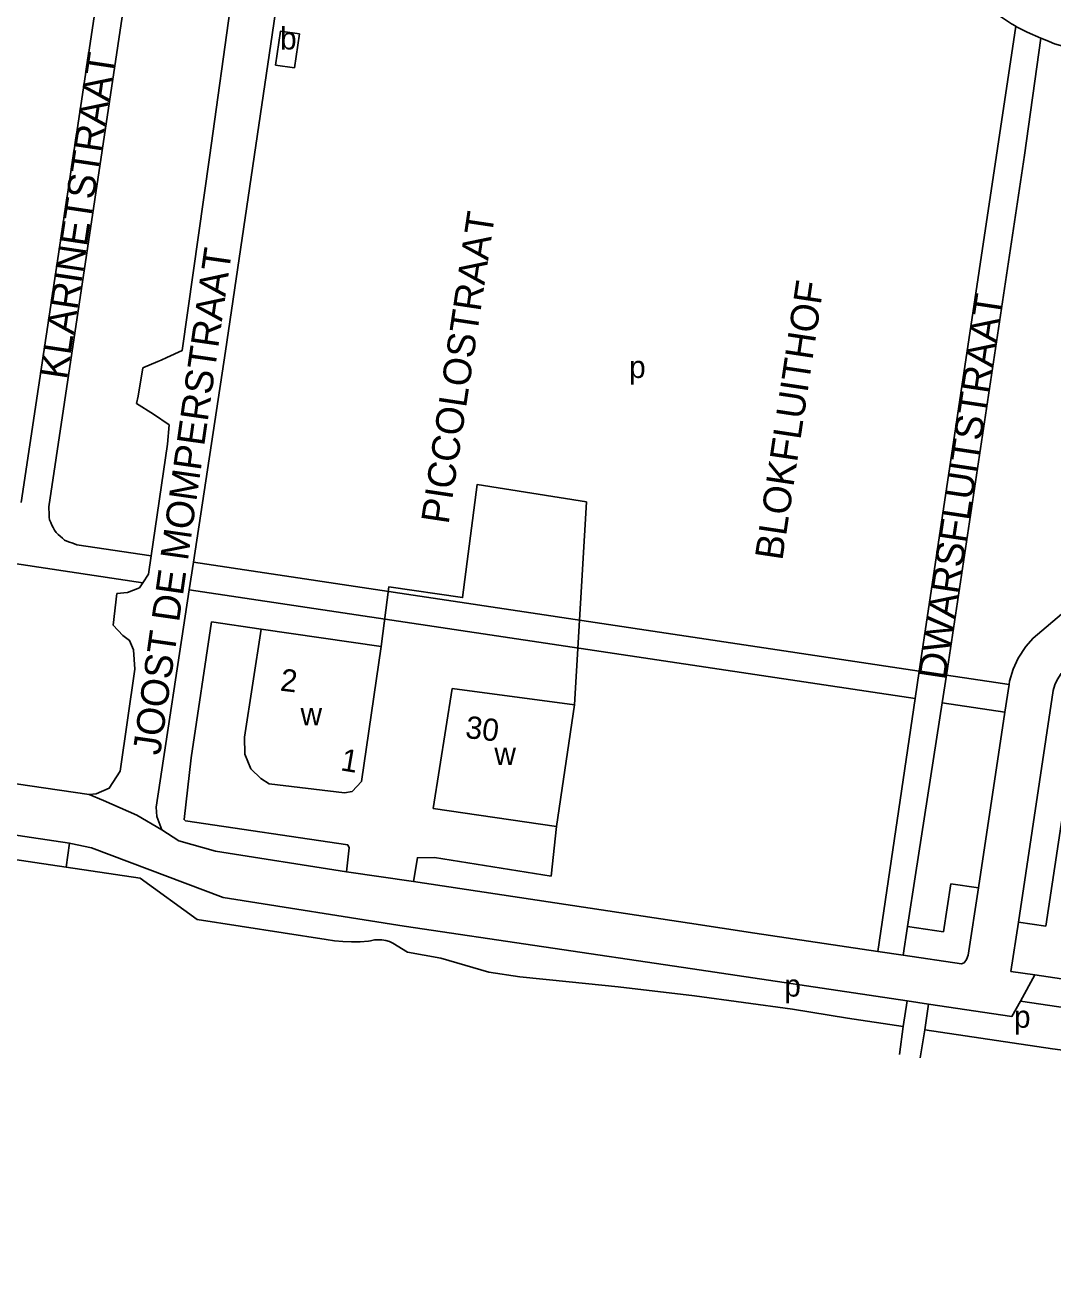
# Model space of a CAD drawing. Extents: x 163012 to 165277, y 382513 to 383987.
# Drawn here: x 164465.3 to 164649.9, y 382601.5 to 382827.9 of the extents above; entities that cross this region are included whole.
import ezdxf

# ---------------------------------------------------------------- set-up
doc = ezdxf.new("R2010")
doc.units = 0
for name, color, linetype in [('BLT_Basislijn', 7, 'Continuous'), ('BLT_Bebouwing', 7, 'Continuous'), ('BLT_Centroide', 7, 'Continuous'), ('BLT_Huisnummer', 7, 'Continuous'), ('BLT_Huisnummer_reeks', 7, 'Continuous'), ('BLT_Plantopo', 7, 'Continuous'), ('BLT_Straatnaam', 7, 'Continuous'), ('BLT_Vlakafsluiter', 7, 'Continuous')]:
    doc.layers.add(name, color=color, linetype=linetype)

msp = doc.modelspace()

# ---------------------------------------------------------------- linework, layer by layer
at = {"layer": 'BLT_Basislijn'}
for p, q in [((164498.41, 382804.11), (164503.27, 382838.72)), ((164644.88, 382804.57), (164647.78, 382825.58)), ((164486.49, 382766.37), (164485.6, 382761.24)), ((164486.49, 382766.37), (164489.17, 382767.47)), ((164485.35, 382759.94), (164485.6, 382761.24)), ((164485.35, 382759.94), (164488.37, 382758.01)), ((164481.81, 382725.81), (164481.16, 382720.15)), ((164481.81, 382725.81), (164483.72, 382726.02)), ((164481.16, 382720.15), (164482.88, 382718.29)), ((164507.71, 382719.39), (164529.29, 382716.27)), ((164542.06, 382708.77), (164538.65, 382687.21)), ((164542.06, 382708.77), (164563.99, 382705.82)), ((164563.99, 382705.82), (164560.8, 382683.95)), ((164538.65, 382687.21), (164560.8, 382683.95)), ((164472.71, 382676.64), (164418.34, 382684.73)), ((164560.8, 382683.95), (164559.83, 382675.03)), ((164472.71, 382676.64), (164473.3, 382680.95)), ((164523.03, 382675.81), (164535.08, 382674.05)), ((164535.08, 382674.05), (164584.68, 382666.58)), ((164631.65, 382673.68), (164636.59, 382672.94)), ((164519.43, 382663.67), (164496.2, 382667.24)), ((164533.41, 382666.08), (164583.59, 382658.63)), ((164623.85, 382665.98), (164623.05, 382660.82)), ((164623.85, 382665.98), (164630.34, 382665.02)), ((164643.76, 382666.8), (164648.7, 382666.05)), ((164596.42, 382664.78), (164618.52, 382661.5)), ((164618.52, 382661.5), (164623.05, 382660.82)), ((164623.05, 382660.82), (164633.54, 382659.27)), ((164583.59, 382658.63), (164623.77, 382652.64)), ((164646.72, 382657.3), (164691.53, 382650.62)), ((164623.09, 382648.02), (164623.77, 382652.64)), ((164626.93, 382647.45), (164627.61, 382652.06)), ((164622.39, 382643.02), (164623.09, 382648.02)), ((164626.12, 382642.42), (164626.93, 382647.45))]:
    msp.add_line(p, q, dxfattribs=at)
for points in [[(164511.39, 382837.58), (164501.34, 382769.35), (164495.56, 382731.44)], [(164639.31, 382830.29), (164642.52, 382828.15), (164643.29, 382827.72)], [(164626.81, 382717.82), (164643.29, 382827.72)], [(164643.29, 382827.72), (164643.45, 382827.63), (164644.38, 382827.11), (164645.33, 382826.62), (164647.78, 382825.58)], [(164647.78, 382825.58), (164648.29, 382825.36), (164649.28, 382824.94), (164650.28, 382824.57), (164651.31, 382824.25), (164652.33, 382823.93), (164653.36, 382823.62), (164654.38, 382823.3), (164655.42, 382823.06), (164656.47, 382822.85), (164657.51, 382822.64), (164658.56, 382822.42), (164659.6, 382822.21)], [(164642.1, 382709.46), (164642.2, 382710.08), (164642.8, 382712.21), (164643.72, 382714.19), (164645.09, 382716.27), (164646.41, 382717.79), (164753.19, 382808.18)], [(164490.8, 382768.2), (164493.55, 382769.49), (164498.41, 382804.11)], [(164644.88, 382804.57), (164630.87, 382711.15)], [(164643.76, 382666.8), (164650.03, 382708.38), (164650.32, 382709.41), (164650.73, 382710.29), (164651.48, 382711.43), (164652.04, 382712.07), (164758.95, 382802.57), (164761.34, 382804.28), (164762.45, 382804.76), (164763.28, 382804.91), (164766.44, 382804.62), (164769.71, 382804.13)], [(164489.17, 382767.47), (164489.76, 382767.72), (164490.8, 382768.2)], [(164487.96, 382732.58), (164490.92, 382752.64), (164491.18, 382756.1), (164488.37, 382758.01)], [(164529.29, 382716.27), (164530.68, 382727.01), (164543.9, 382725.08), (164546.51, 382745.37), (164566.16, 382742.25), (164563.99, 382705.82)], [(164486.46, 382727.74), (164487.47, 382729.3), (164487.96, 382732.58)], [(164495.56, 382731.44), (164494.8, 382726.49)], [(164483.72, 382726.02), (164485.84, 382726.81), (164486.46, 382727.74)], [(164494.8, 382726.49), (164488.85, 382687.46), (164488.96, 382685.77), (164489.89, 382683.35)], [(164187.08, 382723.68), (164473.3, 382680.95)], [(164507.71, 382719.39), (164498.82, 382720.72), (164495.16, 382696.29), (164493.88, 382685.21), (164494.11, 382684.99), (164523.28, 382680.64), (164523.52, 382680.11), (164523.03, 382675.81)], [(164482.88, 382718.29), (164484.08, 382717.37), (164484.78, 382715.68), (164485.03, 382712.22), (164482.37, 382693.89), (164480.43, 382690.85), (164478.1, 382689.83), (164476.83, 382689.72)], [(164507.71, 382719.39), (164504.73, 382699.99), (164504.8, 382696.93), (164505.88, 382694.32), (164507.66, 382692.58), (164509.16, 382691.61), (164522.69, 382689.99), (164524.06, 382690.27), (164525.72, 382692.03), (164529.29, 382716.27)], [(164625.94, 382711.88), (164626.81, 382717.82)], [(164625.21, 382706.94), (164625.94, 382711.88)], [(164630.87, 382711.15), (164630.1, 382706.2)], [(164641.36, 382704.52), (164642.1, 382709.46)], [(164618.52, 382661.5), (164625.21, 382706.94)], [(164630.1, 382706.2), (164625.36, 382675.67)], [(164636.59, 382672.94), (164641.36, 382704.52)], [(164648.7, 382666.05), (164654.21, 382702.59)], [(164476.83, 382689.72), (164421.44, 382697.77), (164396.29, 382701.71)], [(164489.89, 382683.35), (164485.4, 382685.97), (164479.37, 382688.6), (164476.83, 382689.72)], [(164489.89, 382683.35), (164492.94, 382681.36), (164499.51, 382679.52), (164523.03, 382675.81)], [(164473.3, 382680.95), (164473.51, 382680.92), (164477.24, 382680.13), (164500.92, 382671.2)], [(164559.83, 382675.03), (164538.87, 382678.36), (164535.8, 382678.35), (164535.08, 382674.05)], [(164496.2, 382667.24), (164485.99, 382674.7), (164472.71, 382676.64)], [(164625.36, 382675.67), (164623.85, 382665.98)], [(164630.34, 382665.02), (164631.65, 382673.68)], [(164633.54, 382659.27), (164634.02, 382659.44), (164634.45, 382660.08), (164634.77, 382660.86), (164636.59, 382672.94)], [(164500.92, 382671.2), (164533.41, 382666.08)], [(164596.42, 382664.78), (164584.68, 382666.58)], [(164646.72, 382657.3), (164642.42, 382657.94), (164643.76, 382666.8)], [(164527.02, 382663.34), (164525.48, 382663.25), (164523.94, 382663.24), (164522.4, 382663.3), (164520.87, 382663.45), (164519.43, 382663.67)], [(164531.38, 382663.01), (164530.75, 382663.28), (164530.1, 382663.47), (164529.42, 382663.58), (164528.74, 382663.62), (164528.06, 382663.57), (164527.39, 382663.45), (164527.02, 382663.34)], [(164571.88, 382655.18), (164563.03, 382656.07), (164554.17, 382656.95), (164548.63, 382657.78), (164540, 382660.32), (164534.03, 382661.41), (164531.38, 382663.01)], [(164623.09, 382648.02), (164613.09, 382649.5), (164603.16, 382651.17), (164585.55, 382653.57), (164571.88, 382655.18)], [(164623.77, 382652.64), (164627.61, 382652.06)], [(164627.61, 382652.06), (164642.6, 382649.83), (164644.12, 382652.59)], [(164961.8, 382601.46), (164943.21, 382605.16), (164899.78, 382613.32), (164885.12, 382615.78), (164724.57, 382640.36), (164700, 382644.3), (164644.12, 382652.59)], [(164649.92, 382644.03), (164626.93, 382647.45)], [(164732.88, 382630.69), (164719.07, 382633.73), (164695.33, 382636.88), (164692.73, 382637.74), (164675.17, 382640.67), (164669.32, 382641.43), (164649.92, 382644.03)]]:
    msp.add_lwpolyline(points, dxfattribs=at)
at = {"layer": 'BLT_Bebouwing'}
msp.add_line((164513.72, 382820.22), (164514.61, 382826.34), dxfattribs=at)
msp.add_lwpolyline([(164514.61, 382826.34), (164511.2, 382826.83), (164510.31, 382820.72), (164513.72, 382820.22)], dxfattribs=at)
at = {"layer": 'BLT_Plantopo'}
for p, q in [((164479.77, 382843.11), (164464.62, 382742.14)), ((164469.57, 382741.4), (164484.71, 382842.37)), ((164486.46, 382727.74), (164385.73, 382742.85)), ((164487.96, 382732.58), (164474.61, 382734.58)), ((164495.56, 382731.44), (164625.94, 382711.88)), ((164494.8, 382726.49), (164625.21, 382706.94)), ((164639.73, 382709.82), (164630.87, 382711.15)), ((164642.1, 382709.46), (164639.73, 382709.82)), ((164641.36, 382704.52), (164630.1, 382706.2))]:
    msp.add_line(p, q, dxfattribs=at)
msp.add_lwpolyline([(164474.61, 382734.58), (164474.17, 382734.73), (164473.72, 382734.89), (164473.27, 382735.05), (164472.83, 382735.2), (164472.4, 382735.41), (164472.01, 382735.75), (164471.63, 382736.09), (164471.25, 382736.43), (164470.87, 382736.77), (164470.57, 382737.18), (164470.36, 382737.64), (164470.14, 382738.11), (164469.93, 382738.57), (164469.71, 382739.04), (164469.64, 382739.51), (164469.62, 382739.98), (164469.61, 382740.45), (164469.59, 382740.93), (164469.57, 382741.4)], dxfattribs=at)
at = {"layer": 'BLT_Vlakafsluiter'}
msp.add_line((164644.12, 382652.59), (164646.72, 382657.3), dxfattribs=at)

# ---------------------------------------------------------------- texts
at = {"layer": 'BLT_Centroide'}
for s, p in [('b', (164511.12, 382823.53)), ('p', (164573.83, 382764.52)), ('w', (164514.8, 382702.16)), ('w', (164549.63, 382695.02)), ('p', (164601.71, 382653.4)), ('p', (164642.98, 382647.8))]:
    msp.add_text(s, height=4, dxfattribs=at).set_placement(p)
at = {"layer": 'BLT_Huisnummer'}
for s, p in [('2', (164511.01, 382708.38)), ('30', (164544.28, 382699.89))]:
    msp.add_text(s, height=4, rotation=353.1586, dxfattribs=at).set_placement(p)
at = {"layer": 'BLT_Huisnummer_reeks'}
msp.add_text('1', height=4, rotation=350.3103, dxfattribs=at).set_placement((164521.84, 382694.08))
at = {"layer": 'BLT_Straatnaam'}
for s, rotation, p in [('KLARINETSTRAAT', 81.4676, (164472.8, 382764.11)), ('PICCOLOSTRAAT', 81.4676, (164541.38, 382738.12)), ('JOOST DE MOMPERSTRAAT', 81.9014, (164489.57, 382696.63)), ('BLOKFLUITHOF', 81.4676, (164601.35, 382731.62)), ('DWARSFLUITSTRAAT', 81.4715, (164630.64, 382710.13))]:
    msp.add_text(s, height=5, rotation=rotation, dxfattribs=at).set_placement(p)

doc.saveas('drawing.dxf')
